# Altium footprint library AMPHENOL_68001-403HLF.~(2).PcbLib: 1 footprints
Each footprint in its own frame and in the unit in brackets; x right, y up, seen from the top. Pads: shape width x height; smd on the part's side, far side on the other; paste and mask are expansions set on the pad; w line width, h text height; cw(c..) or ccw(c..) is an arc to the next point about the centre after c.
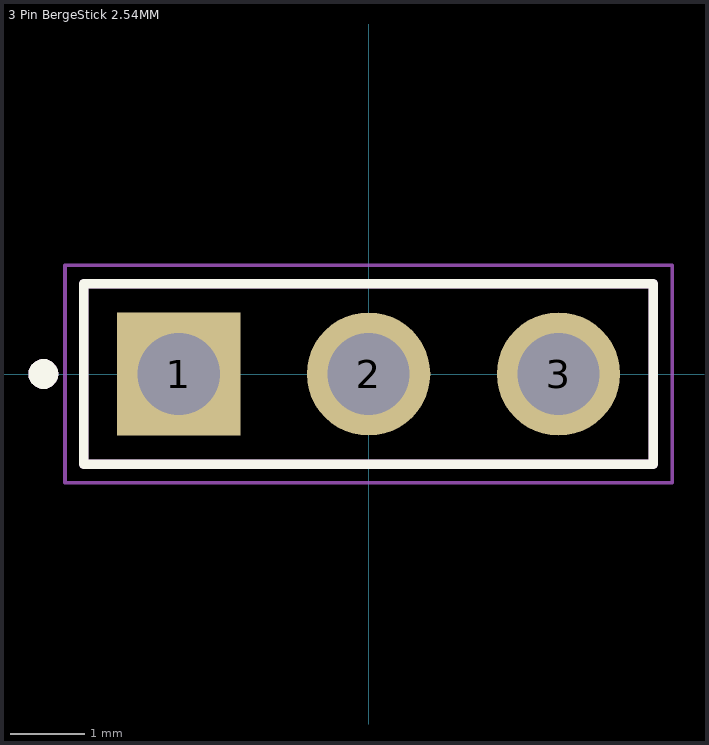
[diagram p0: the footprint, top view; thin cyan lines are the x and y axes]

## 3 Pin BergeStick 2.54MM [mm] "3 Pin 3Pos THT BergeStick 2.54MM Amphenol 68001-403HLF"
height 8.58
pads (3):
  rect 1.65x1.65 / inner round 1.65 / far side rect 1.65x1.65 hole 1.1: 1(-2.54,0)
  round 1.65 hole 1.1: 2(0,0) 3(2.54,0)
Top Overlay:
  circle w0.2: c-4.35,0 r0.1
  lines w0.127: -3.81,-1.205 3.81,-1.205 3.81,1.205 -3.81,1.205 -3.81,-1.205
Mechanical 13:
  circle w0.2: c-4.35,0 r0.1
  lines w0.127: -3.81,-1.205 3.81,-1.205 3.81,1.205 -3.81,1.205 -3.81,-1.205
Mechanical 15:
  lines w0.05: -4.06,-1.455 4.06,-1.455 4.06,1.455 -4.06,1.455 -4.06,-1.455
3D body "step_temp.STEP": height 8.38, standoff -3.05, extent -3.81,-1.205 3.81,1.205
